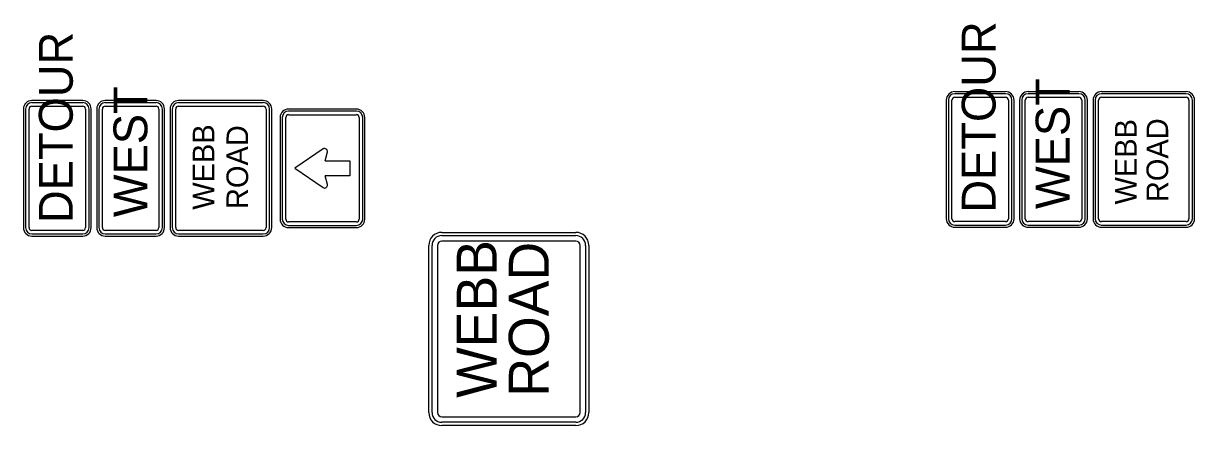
# Model space of a CAD drawing. Extents: x 1123038 to 1172987, y 554419 to 623636.
# Drawn here: x 1156005 to 1160761, y 573461 to 575093 of the extents above; entities that cross this region are included whole.
import ezdxf

# ---------------------------------------------------------------- set-up
doc = ezdxf.new("R2010")
doc.units = 0
doc.layers.add('Default', color=7, linetype='Continuous')
doc.layers.add('SIGNS TRAFFIC', color=7, linetype='Continuous')

msp = doc.modelspace()

# ---------------------------------------------------------------- linework, layer by layer
at = {"layer": 'Default'}
for p, q in [((1159993.7, 574816), (1159787.5, 574816)), ((1160291.6, 574816), (1160085.4, 574816)), ((1160727, 574816), (1160383.3, 574816)), ((1156245.7, 574780), (1156039.4, 574780)), ((1156245.7, 574771.4), (1156039.4, 574771.4)), ((1156543.6, 574780), (1156337.3, 574780)), ((1156543.6, 574771.4), (1156337.3, 574771.4)), ((1156979, 574780), (1156635.2, 574780)), ((1156979, 574771.4), (1156635.2, 574771.4)), ((1159753.1, 574781.7), (1159753.1, 574300.4)), ((1159761.7, 574781.7), (1159761.7, 574300.4)), ((1159776, 574300.4), (1159776, 574781.7)), ((1159993.7, 574807.4), (1159787.5, 574807.4)), ((1159787.5, 574793.1), (1159993.7, 574793.1)), ((1160005.2, 574781.7), (1160005.2, 574300.4)), ((1160019.5, 574300.4), (1160019.5, 574781.7)), ((1160028.1, 574300.4), (1160028.1, 574781.7)), ((1160051, 574781.7), (1160051, 574300.4)), ((1160059.6, 574781.7), (1160059.6, 574300.4)), ((1160073.9, 574300.4), (1160073.9, 574781.7)), ((1160291.6, 574807.4), (1160085.4, 574807.4)), ((1160085.4, 574793.1), (1160291.6, 574793.1)), ((1160303.1, 574781.7), (1160303.1, 574300.4)), ((1160317.4, 574300.4), (1160317.4, 574781.7)), ((1160326, 574300.4), (1160326, 574781.7)), ((1160348.9, 574781.7), (1160348.9, 574300.4)), ((1160357.5, 574781.7), (1160357.5, 574300.4)), ((1160371.8, 574300.4), (1160371.8, 574781.7)), ((1160727, 574807.4), (1160383.3, 574807.4)), ((1160383.3, 574793.1), (1160727, 574793.1)), ((1160738.5, 574781.7), (1160738.5, 574300.4)), ((1160752.8, 574300.4), (1160752.8, 574781.7)), ((1160761.4, 574300.4), (1160761.4, 574781.7)), ((1156005, 574745.7), (1156005, 574264.4)), ((1156013.6, 574745.7), (1156013.6, 574264.4)), ((1156028, 574264.4), (1156028, 574745.7)), ((1156039.4, 574757.1), (1156245.7, 574757.1)), ((1156257.1, 574745.7), (1156257.1, 574264.4)), ((1156271.4, 574264.4), (1156271.4, 574745.7)), ((1156280, 574264.4), (1156280, 574745.7)), ((1156303, 574745.7), (1156303, 574264.4)), ((1156311.6, 574745.7), (1156311.6, 574264.4)), ((1156325.9, 574264.4), (1156325.9, 574745.7)), ((1156337.3, 574757.1), (1156543.6, 574757.1)), ((1156555, 574745.7), (1156555, 574264.4)), ((1156569.4, 574264.4), (1156569.4, 574745.7)), ((1156578, 574264.4), (1156578, 574745.7)), ((1156600.9, 574745.7), (1156600.9, 574264.4)), ((1156609.5, 574745.7), (1156609.5, 574264.4)), ((1156623.8, 574264.4), (1156623.8, 574745.7)), ((1156635.2, 574757.1), (1156979, 574757.1)), ((1156990.5, 574745.7), (1156990.5, 574264.4)), ((1157004.8, 574264.4), (1157004.8, 574745.7)), ((1157013.4, 574264.4), (1157013.4, 574745.7)), ((1157357.1, 574745.7), (1157082.1, 574745.7)), ((1157357.1, 574737.1), (1157082.1, 574737.1)), ((1157082.1, 574722.7), (1157357.1, 574722.7)), ((1157047.7, 574711.3), (1157047.7, 574298.8)), ((1157056.3, 574711.3), (1157056.3, 574298.8)), ((1157070.7, 574298.8), (1157070.7, 574711.3)), ((1157368.6, 574711.3), (1157368.6, 574298.8)), ((1157382.9, 574298.8), (1157382.9, 574711.3)), ((1157391.5, 574298.8), (1157391.5, 574711.3)), ((1157222.1, 574583.5), (1157107.9, 574505)), ((1157231.1, 574535.1), (1157239.4, 574571.2)), ((1157231.1, 574535.1), (1157331.3, 574535.1)), ((1157331.3, 574535.1), (1157331.3, 574474.9)), ((1157107.9, 574505), (1157222.1, 574426.6)), ((1157239.4, 574438.8), (1157231.1, 574474.9)), ((1157331.3, 574474.9), (1157231.1, 574474.9)), ((1157357.1, 574287.3), (1157082.1, 574287.3)), ((1159993.7, 574289), (1159787.5, 574289)), ((1160291.6, 574289), (1160085.4, 574289)), ((1160727, 574289), (1160383.3, 574289)), ((1156245.7, 574252.9), (1156039.4, 574252.9)), ((1156039.4, 574238.6), (1156245.7, 574238.6)), ((1156543.6, 574252.9), (1156337.3, 574252.9)), ((1156337.3, 574238.6), (1156543.6, 574238.6)), ((1156979, 574252.9), (1156635.2, 574252.9)), ((1156635.2, 574238.6), (1156979, 574238.6)), ((1157082.1, 574273), (1157357.1, 574273)), ((1157082.1, 574264.4), (1157357.1, 574264.4)), ((1159787.5, 574274.6), (1159993.7, 574274.6)), ((1159787.5, 574266), (1159993.7, 574266)), ((1160085.4, 574274.6), (1160291.6, 574274.6)), ((1160085.4, 574266), (1160291.6, 574266)), ((1160383.3, 574274.6), (1160727, 574274.6)), ((1160383.3, 574266), (1160727, 574266)), ((1156039.4, 574230), (1156245.7, 574230)), ((1156337.3, 574230), (1156543.6, 574230)), ((1156635.2, 574230), (1156979, 574230))]:
    msp.add_line(p, q, dxfattribs=at)
for centre, radius, start, end in [((1159787.5, 574781.7), 34.4, 90, 180), ((1159993.7, 574781.7), 34.4, 0, 90), ((1160085.4, 574781.7), 34.4, 90, 180), ((1160291.6, 574781.7), 34.4, 0, 90), ((1160383.3, 574781.7), 34.4, 90, 180), ((1160727, 574781.7), 34.4, 0, 90), ((1156039.4, 574745.7), 34.4, 90, 180), ((1156039.4, 574745.7), 25.8, 90, 180), ((1156245.7, 574745.7), 34.4, 0, 90), ((1156245.7, 574745.7), 25.8, 0, 90), ((1156337.3, 574745.7), 34.4, 90, 180), ((1156337.3, 574745.7), 25.8, 90, 180), ((1156543.6, 574745.7), 34.4, 0, 90), ((1156543.6, 574745.7), 25.8, 0, 90), ((1156635.2, 574745.7), 34.4, 90, 180), ((1156635.2, 574745.7), 25.8, 90, 180), ((1156979, 574745.7), 34.4, 0, 90), ((1156979, 574745.7), 25.8, 0, 90), ((1159787.5, 574781.7), 25.8, 90, 180), ((1159787.5, 574781.7), 11.5, 90, 180), ((1159993.7, 574781.7), 25.8, 0, 90), ((1159993.7, 574781.7), 11.5, 0, 90), ((1160085.4, 574781.7), 25.8, 90, 180), ((1160085.4, 574781.7), 11.5, 90, 180), ((1160291.6, 574781.7), 25.8, 0, 90), ((1160291.6, 574781.7), 11.5, 0, 90), ((1160383.3, 574781.7), 25.8, 90, 180), ((1160383.3, 574781.7), 11.5, 90, 180), ((1160727, 574781.7), 25.8, 0, 90), ((1160727, 574781.7), 11.5, 0, 90), ((1156039.4, 574745.7), 11.5, 90, 180), ((1156245.7, 574745.7), 11.5, 0, 90), ((1156337.3, 574745.7), 11.5, 90, 180), ((1156543.6, 574745.7), 11.5, 0, 90), ((1156635.2, 574745.7), 11.5, 90, 180), ((1156979, 574745.7), 11.5, 0, 90), ((1157082.1, 574711.3), 34.4, 90, 180), ((1157082.1, 574711.3), 25.8, 90, 180), ((1157082.1, 574711.3), 11.5, 90, 180), ((1157357.1, 574711.3), 34.4, 0, 90), ((1157357.1, 574711.3), 25.8, 0, 90), ((1157357.1, 574711.3), 11.5, 0, 90), ((1157228.2, 574573.8), 11.5, 347.0497, 122.2757), ((1157228.2, 574436.3), 11.5, 237.7244, 12.9504), ((1157082.1, 574298.8), 34.4, 180, 270), ((1157082.1, 574298.8), 25.8, 180, 270), ((1157082.1, 574298.8), 11.5, 180, 270), ((1157357.1, 574298.8), 34.4, 270, 0), ((1157357.1, 574298.8), 25.8, 270, 0), ((1157357.1, 574298.8), 11.5, 270, 0), ((1159787.5, 574300.4), 34.4, 180, 270), ((1159787.5, 574300.4), 25.8, 180, 270), ((1159787.5, 574300.4), 11.5, 180, 270), ((1159993.7, 574300.4), 34.4, 270, 0), ((1159993.7, 574300.4), 25.8, 270, 0), ((1159993.7, 574300.4), 11.5, 270, 0), ((1160085.4, 574300.4), 34.4, 180, 270), ((1160085.4, 574300.4), 25.8, 180, 270), ((1160085.4, 574300.4), 11.5, 180, 270), ((1160291.6, 574300.4), 34.4, 270, 0), ((1160291.6, 574300.4), 25.8, 270, 0), ((1160291.6, 574300.4), 11.5, 270, 0), ((1160383.3, 574300.4), 34.4, 180, 270), ((1160383.3, 574300.4), 25.8, 180, 270), ((1160383.3, 574300.4), 11.5, 180, 270), ((1160727, 574300.4), 34.4, 270, 0), ((1160727, 574300.4), 25.8, 270, 0), ((1160727, 574300.4), 11.5, 270, 0), ((1156039.4, 574264.4), 34.4, 180, 270), ((1156039.4, 574264.4), 25.8, 180, 270), ((1156039.4, 574264.4), 11.5, 180, 270), ((1156245.7, 574264.4), 34.4, 270, 0), ((1156245.7, 574264.4), 25.8, 270, 0), ((1156245.7, 574264.4), 11.5, 270, 0), ((1156337.3, 574264.4), 34.4, 180, 270), ((1156337.3, 574264.4), 25.8, 180, 270), ((1156337.3, 574264.4), 11.5, 180, 270), ((1156543.6, 574264.4), 34.4, 270, 0), ((1156543.6, 574264.4), 25.8, 270, 0), ((1156543.6, 574264.4), 11.5, 270, 0), ((1156635.2, 574264.4), 34.4, 180, 270), ((1156635.2, 574264.4), 25.8, 180, 270), ((1156635.2, 574264.4), 11.5, 180, 270), ((1156979, 574264.4), 34.4, 270, 0), ((1156979, 574264.4), 25.8, 270, 0), ((1156979, 574264.4), 11.5, 270, 0)]:
    msp.add_arc(centre, radius, start, end, dxfattribs=at)
at = {"layer": 'SIGNS TRAFFIC'}
for points in [[(1157703.9, 574245), (1158248.6, 574245)], [(1157651.2, 573513.6), (1157651.2, 574192.3)], [(1157664.4, 573513.6), (1157664.4, 574192.3)], [(1157686.4, 574192.3), (1157686.4, 573513.6)], [(1157703.9, 574231.8), (1158248.6, 574231.8)], [(1158248.6, 574209.8), (1157703.9, 574209.8)], [(1158266.2, 573513.6), (1158266.2, 574192.3)], [(1158288.1, 574192.3), (1158288.1, 573513.6)], [(1158301.2, 574192.3), (1158301.2, 573513.6)], [(1157703.9, 573496.1), (1158248.6, 573496.1)], [(1158248.6, 573474.2), (1157703.9, 573474.2)], [(1158248.6, 573461), (1157703.9, 573461)]]:
    msp.add_lwpolyline(points, dxfattribs=at)
for centre, radius, start, end in [((1157703.9, 574192.3), 52.6, 90, 180), ((1158248.6, 574192.3), 52.6, 360, 90), ((1157703.9, 574192.3), 39.4, 90, 180), ((1157703.9, 574192.3), 17.5, 90, 180), ((1158248.6, 574192.3), 39.4, 360, 90), ((1158248.6, 574192.3), 17.5, 360, 90), ((1157703.9, 573513.6), 52.6, 180, 270), ((1157703.9, 573513.6), 39.4, 180, 270), ((1157703.9, 573513.6), 17.5, 180, 270), ((1158248.6, 573513.6), 52.6, 270, 0), ((1158248.6, 573513.6), 39.4, 270, 0), ((1158248.6, 573513.6), 17.5, 270, 0)]:
    msp.add_arc(centre, radius, start, end, dxfattribs=at)

# ---------------------------------------------------------------- texts
at = {"layer": 'Default'}
for s, height, p in [('DETOUR', 137.5, (1156205.3, 574282.8)), ('DETOUR', 137.5, (1159953.3, 574325.1)), ('WEST', 137.5, (1160253.5, 574339.7)), ('WEST', 137.5, (1156508.4, 574306.7)), ('WEBB', 88, (1156780.4, 574337)), ('ROAD', 88, (1156917.7, 574339.7)), ('WEBB', 88, (1160526.2, 574358.3)), ('ROAD', 88, (1160654.2, 574367.9))]:
    msp.add_text(s, height=height, rotation=90, dxfattribs=at).set_placement(p)
at = {"layer": 'SIGNS TRAFFIC'}
for s, p in [('WEBB', (1157927.2, 573573.7)), ('ROAD', (1158138.7, 573578.6))]:
    msp.add_text(s, height=162.5, rotation=90, dxfattribs=at).set_placement(p)

doc.saveas('drawing.dxf')
